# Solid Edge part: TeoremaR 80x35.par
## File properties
Title: Terorema R 80x35
Author: DESYS
Template: Normal.par
Last saved by: i.fialdini
Revision: 33
Application: Solid Edge
Stile della faccia: Model Default
Coef. of Thermal Exp: 0.0
Thermal Conductivity: 0.0
Specific Heat: 0.0
Modulus of Elasticity: 0.0
Poisson's Ratio: 0.0
Yield Stress: 0.0
Ultimate Stress: 0.0
Elongation: 0.0
Tipo di contenuto documento: 0
Precisione: 0.990
Document Number: 5003
Revision: 0
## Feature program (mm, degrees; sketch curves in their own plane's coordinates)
sketch for "unnamed Protrusion 1" plane through (0, 0, 0) normal (0, 0, 1) x-axis (1, 0, 0)
  line (-170, -400) -> (170, -400)
  line (170, -400) -> (170, 400)
  line (170, 400) -> (-170, 400)
  line (-170, 400) -> (-170, -400)
  dimension (linear) = 170
  dimension (linear) = 170
extrude "unnamed Protrusion 1" add finite 140 along +normal
lofted cutout "unnamed LoftedCutout 1"
sketch for "ExtrudedCutout_6" plane through (-35, 0, 0) normal (1, 0, 0) x-axis (0, 1, 0)
  line (388, 0) -> (385.8118, 12)
  line (385.8118, 12) -> (-385.8118, 12)
  line (-388, 0) -> (-385.8118, 12)
  line (388, 0) -> (-388, 0)
extrude "ExtrudedCutout_6" cut finite 119 along -normal
sketch for "ExtrudedCutout_2" plane through (0, 0, 140) normal (0, 0, 1) x-axis (0, 1, 0)
  line (-335, -120) -> (335, -120)
  arc centre (335, -105) radius 15 from (335, -120) to (350, -105) ccw
  line (350, -105) -> (350, 150)
  line (-350, 150) -> (350, 150)
  line (-350, 150) -> (-350, -105)
  arc centre (-335, -105) radius 15 from (-350, -105) to (-335, -120) ccw
extrude "ExtrudedCutout_2" cut finite 45 along -normal  DraftAngle = 10 deg
sketch for "Scavo3" plane through (0, 0, 140) normal (0, 0, 1) x-axis (0, -1, 0)
  line (-350, -150) -> (350, -150)
  line (350, -150) -> (350, -50)
  line (350, -50) -> (-350, -50)
  line (-350, -50) -> (-350, -150)
extrude "Scavo3" cut finite 115 along -normal  Treatment1_DraftAngle = 10 deg
fillet "unnamed Round 1"
sketch for "ExtrudedProtrusion_2" plane through (0, 0, 95) normal (0, 0, 1) x-axis (0, -1, 0)
  circle centre (0, 30) radius 35
extrude "ExtrudedProtrusion_2" add finite 40 along +normal
sketch for "ExtrudedProtrusion_3" plane through (0, 0, 0) normal (0, -1, 0) x-axis (1, 0, 0)
  line (5.5887, 125) -> (-30.1784, 125)
  arc centre (-30.1784, 80) radius 45 from (-74.5298, 87.6131) to (-30.1784, 125) cw
  line (-74.5298, 87.6131) -> (-85.2776, 25)
  line (-85.2776, 25) -> (-70.2776, 25)
  line (-70.2776, 25) -> (-60.8489, 78.473)
  arc centre (-41.1527, 75) radius 20 from (-60.8489, 78.473) to (-41.1527, 95) cw
  line (-41.1527, 95) -> (5.5887, 95)
  line (5.5887, 95) -> (5.5887, 125)
  dimension (linear) = 85.2776
extrude "ExtrudedProtrusion_3" add finite 45 symmetric
sketch for "Foro_1" plane through (12.5, 0.0692, 135) normal (0, 0, 1) x-axis (0, -1, 0)
  hole centre (0.0692, 17.5) bore radius 25
hole "Foro_1" diameter 50 through
sketch for "Foro_2" plane through (-35, 0, 46) normal (1, 0, 0) x-axis (0, -1, 0)
  hole centre (0, 4) bore radius 10
hole "Foro_2" diameter 20 finite
fillet "Rotondo_7" radius 5
fillet "Rotondo_14" radius 5
fillet "Rotondo_17" radius 15
fillet "Rotondo_18" radius 6
fillet "Rotondo_19" radius 6
fillet "Rotondo_20" radius 6
sketch for "Foro_4" plane through (-155, 0, 12) normal (0, 0, -1) x-axis (0, -1, 0)
  hole centre (0, -50) bore radius 18
hole "Foro_4" diameter 36 through
fillet "Rotondo_21" radius 15
fillet "Rotondo_22" radius 5
sketch for "Foro_5" plane through (-170, 0, 50) normal (-1, 0, 0) x-axis (0, -1, 0)
  hole centre (-378, 68) bore radius 8
hole "Foro_5" finite
fillet "Rotondo_26" radius 6
sketch for "ExtrudedCutout_7" plane through (-170, 0, 72.5) normal (-1, 0, 0) x-axis (0, 1, 0)
extrude "ExtrudedCutout_7" cut finite 60 along -normal
sketch for "unnamed Cutout 1" #1 plane through (-170, 0, 72.5) normal (-1, 0, 0) x-axis (0, 1, 0)
  line (265, 12.5) -> (255, 12.5)
  arc centre (255, 22.5) radius 10 from (255, 12.5) to (255, 32.5) cw
  line (255, 32.5) -> (265, 32.5)
  arc centre (265, 22.5) radius 10 from (265, 12.5) to (265, 32.5) ccw
sketch for "unnamed Cutout 1" #2 plane through (-170, 0, 72.5) normal (-1, 0, 0) x-axis (0, 1, 0)
  line (-265, 12.5) -> (-255, 12.5)
  line (-255, 32.5) -> (-265, 32.5)
  dimension (linear) = 255
  dimension (linear) = 255
extrude "unnamed Cutout 1" cut through along -normal
fillet "Rotondo_31" radius 15
fillet "Rotondo_32" radius 5
fillet "Rotondo_33" radius 5
fillet "Rotondo_34" radius 5
fillet "Rotondo_35" radius 5
fillet "Rotondo_36" radius 5
fillet "Rotondo_37" radius 5
fillet "Rotondo_38" radius 5
fillet "Rotondo_39" radius 2
fillet "Rotondo_41" radius 5
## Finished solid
Body 1: solid body, 165 faces, 364 edges, 200 vertices.
  Faces by surface: cylinder 75, plane 31, blend 24, torus 23, sphere 10, cone 2
  Edges by curve: circle 156, line 149, ellipse 54, intersection 5
Bounding box of the edges (mm; curved faces can reach further): 340.000 x 800.000 x 140.000, from (-170, -400, 0) to (170, 400, 140).
Cylindrical faces by radius (mm): R5 x42, R6 x14, R8 x1, R10 x5, R15 x6, R18 x1, R20 x2, R25 x1, R35 x1, R45 x1, R121.875 x1
Conical faces (half-angle, radius in mm at the cone's reference point): 10 deg R15 x2
Toroidal faces (ring radius, tube radius in mm): R1 r5 x8, R2.8698 r5 x2, R12 r2 x1, R19.1955 r5 x2, R23 r5 x1, R25 r5 x2, R30 r5 x1, R40 r5 x4, R40 r15 x1, R126.875 r5 x1
Spherical faces by radius (mm): R5 x10
Planar faces by outward normal: +x 3, +y 2, +z 7, -x 2, -y 2, -z 5, oblique 10
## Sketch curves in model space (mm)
line (138, -372.5, 85) -> (-35, -372.5, 85)
line (-35, -372.5, 85) -> (-35, 372.5, 85)
line (-35, 372.5, 85) -> (138, 372.5, 85)
line (138, 372.5, 85) -> (138, -372.5, 85)
line (158, -388, 0) -> (-35, -388, 0)
line (-35, -388, 0) -> (-35, 388, 0)
line (-35, 388, 0) -> (158, 388, 0)
line (158, 388, 0) -> (158, -388, 0)
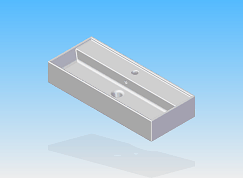
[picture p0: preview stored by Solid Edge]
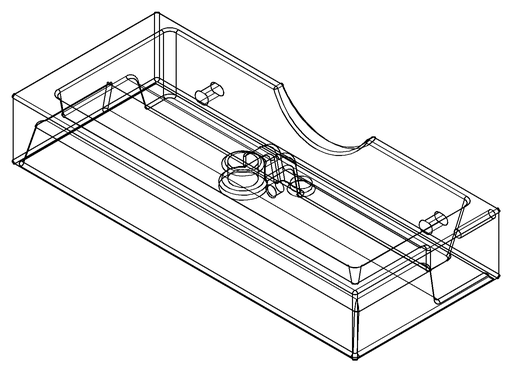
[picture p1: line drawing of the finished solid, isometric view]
